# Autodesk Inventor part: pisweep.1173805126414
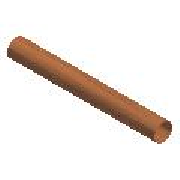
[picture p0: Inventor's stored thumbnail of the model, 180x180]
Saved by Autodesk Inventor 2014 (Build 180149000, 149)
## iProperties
NAME: PIPING: ASTM B 88 Tube
DATA: <meta><inlinegroups number="1" deflen="254"></inlinegroups><connections number="2"></connections><angles><a>3.14159265358979</a></angles></meta>
Company: Autodesk, Inc.
Created: 2007-02
Material: Copper
Description: Pipe
Document SubType Name: Modeling
Standard: ASTM B 88
Designer: Autodesk, Inc.
Standard Revision: 2003
Standards Organization: ANSI
Language: en-US
Size Designation: 1/2 - Type L - 100
Categories: <MemberInstance><Categories><Category DisplayName="Tube &amp; Pipe" InternalName="4347fa0f-2144-441d-94cd-e3e15c92b736" Mnemonic="TUBEANDPIPE"><CategoryParamete
Stock Number: ASTM B 88 Tube 1/2 - Type L
Density: 8.94 g/cm^3
Mass: 186.829 g
Surface Area: 412.329 cm^2
Volume: 20.8981 cm^3
Appearance: Copper
L: 17.348 in
PL: 17.348 in
Author: Autodesk, Inc.
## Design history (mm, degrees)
sketch "3D Sketch1" dims "d4" = 50.7999, "d5" = 50.7999
workpoint "Work Point3"
workpoint "Work Point4"
workpoint "Work Point5"
workpoint "Work Point6"
workplane "Work Plane1"
sketch "Sketch3"
  geometry: C1 r 7.938 at (0, 0); C2 r 6.922 at (0, 0); 1 further point
  constraints: 2 centre point
workpoint "Work Point7"
sweep "Sweep1" dims "d6" = 0
body "Solid1"
other parameters: "OD" = 15.875 [user parameter], "t" = 1.016 [user parameter], "L" = 440.6392 (= PL) [user parameter], "ID" = 13.843 [user parameter], "PL" = 440.6392 [user parameter; used in 1 equation term], "Size_Designation" = 12.345 [user parameter]
